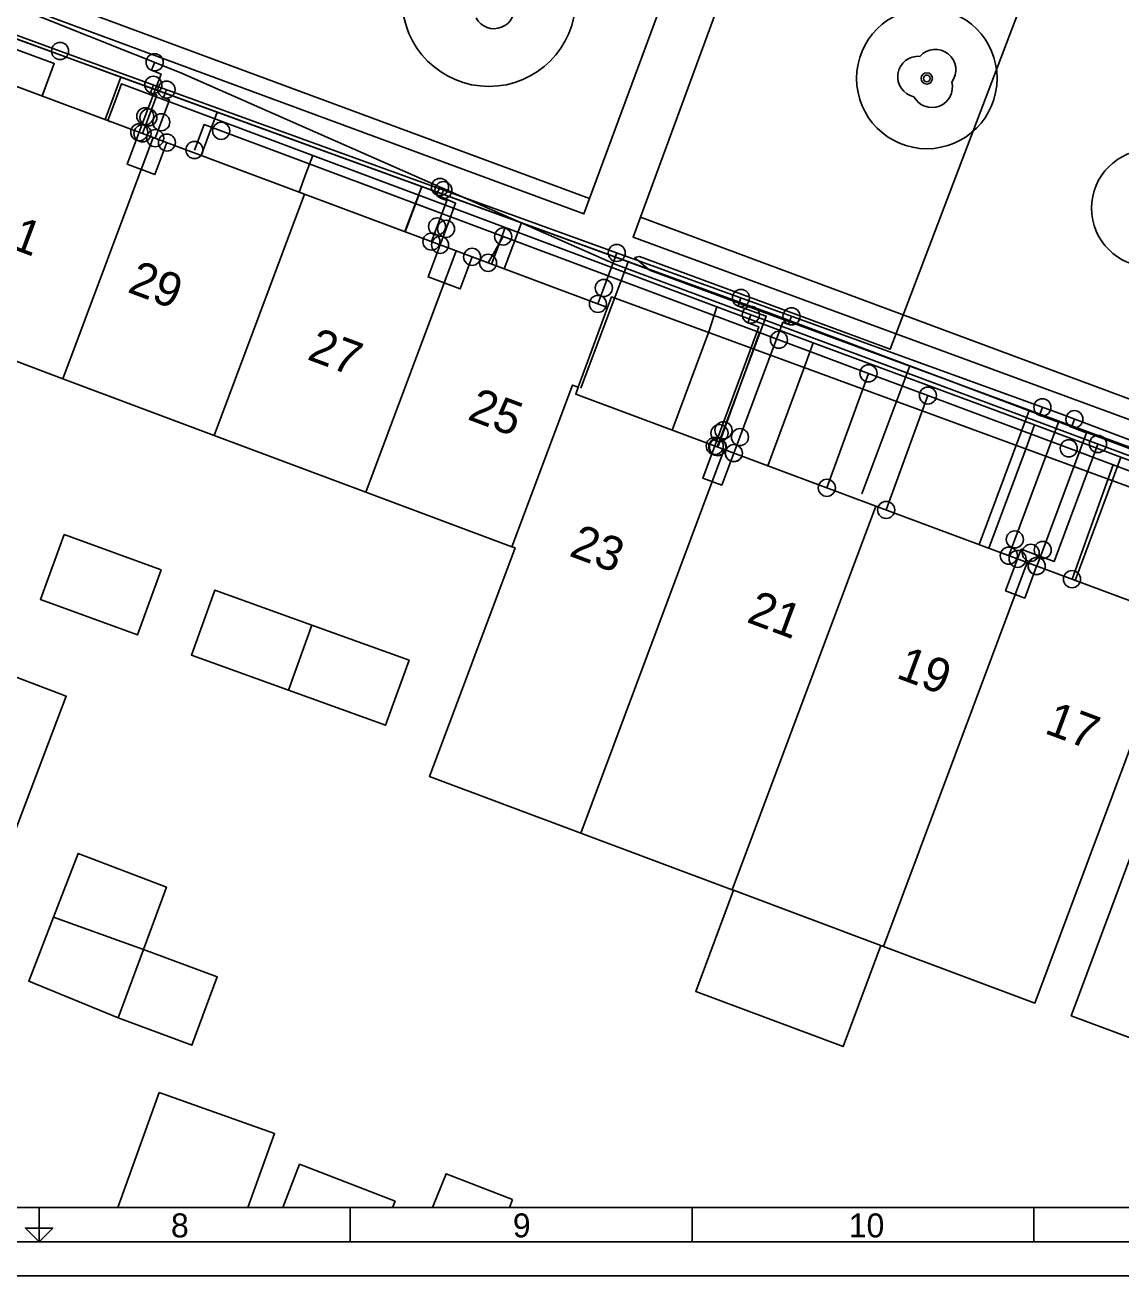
# Model space of a CAD drawing. Extents: x 192672 to 192910, y 446344 to 446512.
# Drawn here: x 192741.13 to 192773.19, y 446343.56 to 446380.14 of the extents above; entities that cross this region are included whole.
import ezdxf

# ---------------------------------------------------------------- set-up
doc = ezdxf.new("R2010")
doc.units = 0
for name, color, linetype in [('( Toegevoegd 29-11-2021 14_41_42) wegdeel vlak', 7, 'Continuous'), ('1010 viewport', 7, 'Continuous'), ('B-GV-GR-BOOM-S', 7, 'Continuous'), ('B-OI-KL-()_MANTELBUIS_WATER-G', 7, 'Continuous'), ('B-OI-KL-BUISLEIDING_OLIEGASCHEMICALIEN_GASLAGEDRUK-G', 7, 'Continuous'), ('B-OI-KL-DATA-G', 7, 'Continuous'), ('B-OI-KL-DATA_GTWP-S', 7, 'Continuous'), ('B-OI-KL-DATA_KABELBED-G', 7, 'Continuous'), ('B-OI-KL-DATA_MOF-S', 7, 'Continuous'), ('B-OI-KL-ET_LS-G', 7, 'Continuous'), ('B-OI-KL-ET_LS_DELIVERYPOINT-S', 7, 'Continuous'), ('B-OI-KL-ET_LS_MOF-S', 7, 'Continuous'), ('B-OI-KL-GAS_LD_AFTAKZADEL-S', 7, 'Continuous'), ('B-OI-KL-GAS_LD_DELIVERYPOINT-S', 7, 'Continuous'), ('B-OI-KL-GAS_LD_OVERGANGSSTUK-S', 7, 'Continuous'), ('B-OI-KL-WATER-G', 7, 'Continuous'), ('boom', 7, 'Continuous'), ('Default', 7, 'Continuous'), ('grens niveau plus 1', 7, 'Continuous'), ('huisnummerreeks BGT', 7, 'Continuous'), ('Luifel', 7, 'Continuous'), ('pand op maaiveld vlak', 7, 'Continuous'), ('straatnaam', 7, 'Continuous'), ('verkeerseiland - berm', 7, 'Continuous'), ('X-XX-AL-TEKENBLAD-S', 7, 'Continuous')]:
    doc.layers.add(name, color=color, linetype=linetype)

# ---------------------------------------------------------------- blocks, each defined once
blk = doc.blocks.new('B-OI-KL-GAS_LD_AFTAKZADEL-S')
at = {"layer": 'Default'}
blk.add_circle((0, 0), 0.25, dxfattribs=at)
blk = doc.blocks.new('B-OI-KL-GAS_LD_DELIVERYPOINT-S')
at = {"layer": 'Default'}
blk.add_circle((0, 0), 0.25, dxfattribs=at)
blk = doc.blocks.new('B-OI-KL-GAS_LD_OVERGANGSSTUK-S')
at = {"layer": 'Default'}
blk.add_circle((0, 0), 0.25, dxfattribs=at)
blk = doc.blocks.new('B-OI-KL-ET_LS_DELIVERYPOINT-S')
at = {"layer": 'Default'}
blk.add_circle((0, 0), 0.25, dxfattribs=at)
blk = doc.blocks.new('B-OI-KL-ET_LS_MOF-S')
at = {"layer": 'Default'}
blk.add_circle((0, 0), 0.25, dxfattribs=at)
blk = doc.blocks.new('B-OI-KL-DATA_GTWP-S')
at = {"layer": 'Default'}
blk.add_circle((0, 0), 0.25, dxfattribs=at)
blk = doc.blocks.new('B-OI-KL-DATA_MOF-S')
at = {"layer": 'Default'}
blk.add_circle((0, 0), 0.25, dxfattribs=at)

msp = doc.modelspace()

# ---------------------------------------------------------------- linework, layer by layer
at = {"layer": '( Toegevoegd 29-11-2021 14_41_42) wegdeel vlak'}
for points in [[(192744.875, 446390.822), (192741.123, 446380.652), (192757.478, 446374.617), (192757.644, 446375.067)], [(192759.13, 446374.517), (192758.916, 446373.935), (192776.422, 446367.504), (192776.611, 446368.02)], [(192758.17, 446371.875), (192758.285, 446372.185), (192775.949, 446365.705), (192777.106, 446365.279), (192794.631, 446358.595), (192794.529, 446358.306)]]:
    msp.add_lwpolyline(points, dxfattribs=at)
at = {"layer": '1010 viewport'}
msp.add_lwpolyline([(192675.743, 446509.756), (192860.643, 446509.756), (192860.643, 446345.556), (192675.743, 446345.556)], close=True, dxfattribs=at)
at = {"layer": 'B-GV-GR-BOOM-S'}
for centre, radius in [((192754.7, 446380.881), 2.539), ((192767.508, 446378.575), 2.054), ((192767.508, 446378.575), 0.164), ((192774.039, 446374.78), 1.713)]:
    msp.add_circle(centre, radius, dxfattribs=at)
at = {"layer": 'B-OI-KL-()_MANTELBUIS_WATER-G'}
msp.add_lwpolyline([(192741.735, 446378.347), (192741.63, 446378.066)], dxfattribs=at)
at = {"layer": 'B-OI-KL-BUISLEIDING_OLIEGASCHEMICALIEN_GASLAGEDRUK-G'}
for points in [[(192742.155, 446379.378), (192739.841, 446380.217), (192739.671, 446379.747)], [(192814.329, 446352.769), (192812.29, 446353.505), (192799.482, 446358.316), (192779.419, 446365.745), (192771.402, 446368.773), (192742.155, 446379.378)], [(192744.883, 446378.389), (192744.798, 446378.154), (192744.984, 446378.086), (192744.74, 446377.435)], [(192745.269, 446378.249), (192745.184, 446378.014), (192745.36, 446377.95), (192745.115, 446377.295)], [(192744.74, 446377.435), (192744.565, 446376.968)], [(192745.115, 446377.295), (192744.94, 446376.828)], [(192753.369, 446375.311), (192753.283, 446375.076), (192753.464, 446375.011), (192753.182, 446374.246)], [(192753.182, 446374.246), (192753.017, 446373.804)], [(192758.439, 446373.473), (192758.061, 446372.448)], [(192758.061, 446372.448), (192757.887, 446371.981)], [(192762.071, 446372.156), (192761.986, 446371.921), (192762.809, 446371.623), (192761.56, 446368.286)], [(192763.551, 446371.619), (192763.466, 446371.384), (192763.298, 446371.445), (192762.041, 446368.087)], [(192770.888, 446368.959), (192770.803, 446368.724), (192771.364, 446368.52), (192770.082, 446365.096)], [(192771.826, 446368.613), (192771.738, 446368.379), (192772.181, 446368.212), (192770.899, 446364.785)], [(192761.56, 446368.286), (192761.379, 446367.8)], [(192762.041, 446368.087), (192761.866, 446367.618)], [(192770.082, 446365.096), (192769.906, 446364.621)], [(192770.899, 446364.785), (192770.724, 446364.316)]]:
    msp.add_lwpolyline(points, dxfattribs=at)
at = {"layer": 'B-OI-KL-DATA-G'}
for points in [[(192777.905, 446365.29), (192778.164, 446365.987), (192777.507, 446366.23), (192773.332, 446367.794), (192762.994, 446371.683), (192740.707, 446379.788), (192739.862, 446380.106), (192736.793, 446371.939), (192730.818, 446355.23), (192731.661, 446354.909)], [(192731.661, 446354.909), (192730.818, 446355.23), (192736.793, 446371.939), (192739.862, 446380.106), (192740.707, 446379.788), (192762.994, 446371.683), (192773.332, 446367.794), (192777.507, 446366.23), (192792.515, 446360.708), (192794.868, 446359.138), (192813.343, 446352.261), (192813.029, 446351.418), (192812.66, 446350.461), (192825.476, 446345.665), (192825.435, 446345.556)], [(192825.435, 446345.556), (192825.476, 446345.665), (192812.66, 446350.461), (192813.029, 446351.418), (192813.343, 446352.261), (192794.868, 446359.138), (192792.515, 446360.708), (192777.507, 446366.23), (192773.332, 446367.794), (192762.994, 446371.683), (192740.707, 446379.788), (192739.862, 446380.106), (192736.793, 446371.939), (192730.818, 446355.23), (192731.661, 446354.909)], [(192731.661, 446354.909), (192730.818, 446355.23), (192736.793, 446371.939), (192739.862, 446380.106), (192740.707, 446379.788), (192762.994, 446371.683), (192773.332, 446367.794), (192777.507, 446366.23), (192792.515, 446360.708), (192794.868, 446359.138), (192813.343, 446352.261), (192813.029, 446351.418), (192812.66, 446350.461), (192825.476, 446345.665), (192825.435, 446345.556)], [(192825.435, 446345.556), (192825.476, 446345.665), (192812.66, 446350.461), (192813.029, 446351.418), (192813.343, 446352.261), (192794.868, 446359.138), (192792.515, 446360.708), (192777.507, 446366.23), (192773.332, 446367.794), (192762.994, 446371.683), (192740.707, 446379.788), (192739.862, 446380.106), (192736.793, 446371.939), (192730.818, 446355.23), (192731.661, 446354.909)], [(192825.435, 446345.556), (192825.476, 446345.665), (192812.66, 446350.461), (192813.029, 446351.418), (192813.343, 446352.261), (192794.868, 446359.138), (192792.515, 446360.708), (192777.507, 446366.23), (192773.332, 446367.794), (192762.994, 446371.683), (192740.707, 446379.788), (192739.862, 446380.106), (192736.793, 446371.939), (192730.818, 446355.23), (192731.661, 446354.909)], [(192825.435, 446345.556), (192825.476, 446345.665), (192812.66, 446350.461), (192813.029, 446351.418), (192813.343, 446352.261), (192794.868, 446359.138), (192792.515, 446360.708), (192777.507, 446366.23), (192773.332, 446367.794), (192762.994, 446371.683), (192740.707, 446379.788), (192739.862, 446380.106), (192736.793, 446371.939), (192730.818, 446355.23), (192731.661, 446354.909)], [(192825.435, 446345.556), (192825.476, 446345.665), (192812.66, 446350.461), (192813.029, 446351.418), (192813.343, 446352.261), (192794.868, 446359.138), (192792.515, 446360.708), (192777.507, 446366.23), (192773.332, 446367.794), (192762.994, 446371.683), (192740.707, 446379.788), (192739.862, 446380.106), (192736.793, 446371.939), (192730.818, 446355.23), (192731.661, 446354.909)], [(192731.661, 446354.909), (192730.818, 446355.23), (192736.793, 446371.939), (192739.862, 446380.106), (192740.707, 446379.788), (192762.994, 446371.683), (192773.332, 446367.794), (192777.507, 446366.23), (192792.515, 446360.708), (192794.868, 446359.138), (192813.343, 446352.261), (192813.029, 446351.418), (192812.66, 446350.461), (192825.476, 446345.665), (192825.435, 446345.556)], [(192731.661, 446354.909), (192730.818, 446355.23), (192736.793, 446371.939), (192739.862, 446380.106), (192740.707, 446379.788), (192762.994, 446371.683), (192773.332, 446367.794), (192777.507, 446366.23), (192792.515, 446360.708), (192794.868, 446359.138), (192813.343, 446352.261), (192813.029, 446351.418), (192812.66, 446350.461), (192825.476, 446345.665), (192825.435, 446345.556)], [(192825.435, 446345.556), (192825.476, 446345.665), (192812.66, 446350.461), (192813.029, 446351.418), (192813.343, 446352.261), (192794.868, 446359.138), (192792.515, 446360.708), (192777.507, 446366.23), (192773.332, 446367.794), (192762.994, 446371.683), (192740.707, 446379.788), (192739.862, 446380.106), (192736.793, 446371.939), (192730.818, 446355.23), (192731.661, 446354.909)], [(192825.435, 446345.556), (192825.476, 446345.665), (192812.66, 446350.461), (192813.029, 446351.418), (192813.343, 446352.261), (192794.868, 446359.138), (192792.515, 446360.708), (192777.507, 446366.23), (192773.332, 446367.794), (192762.994, 446371.683), (192740.707, 446379.788), (192739.862, 446380.106), (192736.793, 446371.939), (192730.818, 446355.23), (192731.661, 446354.909)], [(192777.905, 446365.29), (192778.164, 446365.987), (192777.507, 446366.23), (192773.332, 446367.794), (192762.994, 446371.683), (192740.707, 446379.788), (192739.862, 446380.106), (192736.793, 446371.939), (192732.637, 446360.318), (192733.582, 446359.958)], [(192777.905, 446365.29), (192778.164, 446365.987), (192777.507, 446366.23), (192773.332, 446367.794), (192762.994, 446371.683), (192743.934, 446378.615), (192743.471, 446377.378)], [(192749.547, 446376.324), (192743.956, 446378.419), (192743.764, 446377.908), (192743.555, 446377.346)], [(192777.905, 446365.29), (192778.164, 446365.987), (192777.507, 446366.23), (192773.332, 446367.794), (192762.994, 446371.683), (192746.754, 446377.589), (192746.281, 446376.326)], [(192743.6, 446377.3), (192743.555, 446377.346)], [(192749.547, 446376.324), (192749.357, 446375.815), (192749.146, 446375.253)], [(192752.653, 446375.164), (192749.547, 446376.324)], [(192777.905, 446365.29), (192778.164, 446365.987), (192777.507, 446366.23), (192773.332, 446367.794), (192762.994, 446371.683), (192752.734, 446375.414), (192752.241, 446374.095)], [(192752.653, 446375.164), (192752.251, 446374.091)], [(192755.178, 446374.215), (192752.653, 446375.164)], [(192777.905, 446365.29), (192778.164, 446365.987), (192777.507, 446366.23), (192773.332, 446367.794), (192762.994, 446371.683), (192755.648, 446374.354), (192755.144, 446373.008)], [(192755.178, 446374.215), (192754.988, 446373.707), (192754.778, 446373.145)], [(192761.365, 446371.892), (192755.178, 446374.215)], [(192777.905, 446365.29), (192778.164, 446365.987), (192777.507, 446366.23), (192773.332, 446367.794), (192762.994, 446371.683), (192758.775, 446373.217), (192757.385, 446369.519)], [(192761.365, 446371.892), (192761.139, 446371.191), (192760.058, 446368.293)], [(192764.185, 446370.844), (192761.365, 446371.892)], [(192764.185, 446370.844), (192763.932, 446370.14), (192762.855, 446367.25)], [(192770.655, 446368.444), (192764.185, 446370.844)], [(192777.905, 446365.29), (192778.164, 446365.987), (192777.507, 446366.23), (192773.332, 446367.794), (192767.014, 446370.171), (192765.606, 446366.426)], [(192777.905, 446365.29), (192778.164, 446365.987), (192777.507, 446366.23), (192773.332, 446367.794), (192770.497, 446368.861), (192769.037, 446364.945)], [(192770.655, 446368.444), (192770.417, 446367.768), (192769.325, 446364.838)], [(192773.185, 446367.497), (192770.655, 446368.444)], [(192773.185, 446367.497), (192772.921, 446366.782), (192771.846, 446363.898)], [(192780.217, 446364.871), (192773.185, 446367.497)]]:
    msp.add_lwpolyline(points, dxfattribs=at)
at = {"layer": 'B-OI-KL-DATA_KABELBED-G'}
for points in [[(192743.934, 446378.615), (192739.862, 446380.106), (192736.793, 446371.939), (192732.637, 446360.318)], [(192743.934, 446378.615), (192743.471, 446377.378)], [(192746.754, 446377.589), (192743.934, 446378.615)], [(192746.754, 446377.589), (192746.281, 446376.326)], [(192752.734, 446375.414), (192746.754, 446377.589)], [(192812.803, 446351.5), (192812.464, 446352.48), (192806.244, 446354.809), (192799.501, 446357.334), (192790.741, 446360.614), (192790.377, 446360.75), (192789.321, 446361.146), (192788.597, 446361.417), (192785.666, 446362.514), (192777.496, 446365.573), (192777.131, 446365.71), (192772.96, 446367.272), (192771.66, 446367.759), (192767.539, 446369.302), (192765.803, 446369.952), (192763.181, 446370.934), (192762.609, 446371.148), (192755.115, 446373.954), (192746.365, 446377.23), (192746.085, 446376.483)], [(192752.734, 446375.414), (192752.241, 446374.095)], [(192755.648, 446374.354), (192752.734, 446375.414)], [(192755.648, 446374.354), (192755.144, 446373.008)], [(192758.775, 446373.217), (192755.648, 446374.354)], [(192755.115, 446373.954), (192754.675, 446373.184)], [(192758.775, 446373.217), (192757.385, 446369.519)], [(192767.014, 446370.171), (192758.775, 446373.217)], [(192763.181, 446370.934), (192762.609, 446371.148), (192761.398, 446367.793)], [(192765.803, 446369.952), (192764.584, 446366.605)], [(192767.014, 446370.171), (192765.606, 446366.426)], [(192770.497, 446368.861), (192767.014, 446370.171)], [(192767.539, 446369.302), (192766.32, 446365.958)], [(192770.497, 446368.861), (192769.037, 446364.945)], [(192775.977, 446366.803), (192770.497, 446368.861)], [(192771.66, 446367.759), (192772.96, 446367.272), (192771.755, 446363.932)]]:
    msp.add_lwpolyline(points, dxfattribs=at)
at = {"layer": 'B-OI-KL-ET_LS-G'}
for points in [[(192773.186, 446389.136), (192773.068, 446389.1), (192772.926, 446389.144), (192770.278, 446380.756), (192766.438, 446370.656), (192759.102, 446373.366), (192758.958, 446373.34)], [(192812.885, 446353.609), (192808.475, 446355.248), (192804.025, 446356.797), (192795.126, 446359.954), (192777.441, 446366.051), (192758.408, 446373.136), (192745.69, 446378.74), (192740.34, 446380.878), (192731.982, 446384.732), (192732.765, 446387.575)], [(192744.922, 446379.047), (192744.83, 446378.815), (192745.108, 446378.703), (192744.646, 446377.471)], [(192744.646, 446377.471), (192744.472, 446377.003)], [(192744.472, 446377.003), (192744.121, 446376.067), (192744.93, 446375.764), (192745.28, 446376.701)], [(192753.268, 446375.401), (192753.168, 446375.172), (192753.726, 446374.926), (192753.446, 446374.178)], [(192753.446, 446374.178), (192753.271, 446373.709)], [(192753.271, 446373.709), (192752.92, 446372.773), (192753.857, 446372.422), (192754.207, 446373.359)], [(192758.958, 446373.34), (192759.392, 446372.967), (192781.93, 446364.664)], [(192762.36, 446371.665), (192762.273, 446371.43), (192762.59, 446371.312), (192761.444, 446368.203)], [(192761.444, 446368.203), (192761.304, 446367.828)], [(192761.304, 446367.828), (192760.955, 446366.891), (192761.514, 446366.682), (192761.864, 446367.619)], [(192772.514, 446367.885), (192771.23, 446364.453), (192770.548, 446364.702)], [(192770.548, 446364.702), (192770.267, 446364.807), (192770.162, 446364.526)], [(192770.162, 446364.526), (192769.813, 446363.589), (192770.372, 446363.38), (192770.721, 446364.317)]]:
    msp.add_lwpolyline(points, dxfattribs=at)
at = {"layer": 'B-OI-KL-WATER-G'}
msp.add_lwpolyline([(192730.071, 446383.458), (192740.795, 446379.447), (192741.984, 446379.012), (192741.63, 446378.066)], dxfattribs=at)
at = {"layer": 'boom'}
msp.add_circle((192767.508, 446378.575), 0.1, dxfattribs=at)
for centre, radius, start, end in [((192754.85, 446380.631), 0.6, 208.5058, 13.8356), ((192767.758, 446378.825), 0.6, 323.5446, 138.4658), ((192767.258, 446378.625), 0.6, 85.137, 257.7544), ((192767.508, 446378.575), 0.1, 0, 180), ((192767.658, 446378.325), 0.6, 208.5058, 13.8356), ((192767.508, 446378.575), 0.1, 180, 0)]:
    msp.add_arc(centre, radius, start, end, dxfattribs=at)
at = {"layer": 'grens niveau plus 1'}
msp.add_line((192745.049, 446348.922), (192743.84, 446345.556), dxfattribs=at)
msp.add_lwpolyline([(192747.65, 446345.556), (192748.43, 446347.726), (192745.049, 446348.922)], dxfattribs=at)
at = {"layer": 'Luifel'}
for points in [[(192766.166, 446353.222), (192765.058, 446350.263), (192760.747, 446351.877), (192761.855, 446354.836)], [(192743.852, 446351.105), (192746.012, 446350.305), (192746.753, 446352.307), (192744.593, 446353.107)]]:
    msp.add_lwpolyline(points, dxfattribs=at)
at = {"layer": 'pand op maaiveld vlak'}
for p, q in [((192740.444, 446378.51), (192744.876, 446376.852)), ((192744.876, 446376.852), (192742.235, 446369.796)), ((192749.307, 446375.193), (192744.876, 446376.852)), ((192749.307, 446375.193), (192746.666, 446368.138)), ((192749.307, 446375.193), (192753.739, 446373.534)), ((192753.739, 446373.534), (192751.098, 446366.48)), ((192753.739, 446373.534), (192758.17, 446371.875)), ((192758.17, 446371.875), (192757.312, 446369.547)), ((192737.803, 446371.456), (192742.235, 446369.796)), ((192742.235, 446369.796), (192746.666, 446368.138)), ((192746.666, 446368.138), (192751.098, 446366.48)), ((192757.388, 446356.507), (192761.585, 446367.723)), ((192761.585, 446367.723), (192766.014, 446366.072)), ((192755.366, 446364.882), (192751.098, 446366.48)), ((192766.014, 446366.072), (192761.814, 446354.851)), ((192770.443, 446364.421), (192766.014, 446366.072)), ((192766.241, 446353.194), (192770.443, 446364.421)), ((192749.523, 446362.586), (192748.837, 446360.686)), ((192757.388, 446356.507), (192761.814, 446354.851)), ((192761.855, 446354.836), (192761.814, 446354.851)), ((192766.166, 446353.222), (192761.855, 446354.836)), ((192744.593, 446353.107), (192741.961, 446354.044)), ((192743.852, 446351.105), (192744.593, 446353.107)), ((192766.241, 446353.194), (192766.166, 446353.222)), ((192749.154, 446346.827), (192748.671, 446345.556)), ((192755.301, 446345.556), (192755.392, 446345.788))]:
    msp.add_line(p, q, dxfattribs=at)
for points in [[(192755.366, 446364.882), (192757.145, 446369.61), (192757.312, 446369.547)], [(192761.585, 446367.723), (192757.237, 446369.345), (192757.312, 446369.547)], [(192742.273, 446365.238), (192741.579, 446363.341), (192744.415, 446362.304), (192745.109, 446364.201), (192742.273, 446365.238)], [(192755.366, 446364.882), (192755.462, 446364.846), (192752.961, 446358.164), (192757.388, 446356.507)], [(192766.241, 446353.194), (192770.667, 446351.537), (192774.871, 446362.77), (192770.443, 446364.421)], [(192740.119, 446354.688), (192742.334, 446360.51), (192734.872, 446363.349)], [(192749.523, 446362.586), (192746.682, 446363.612), (192745.996, 446361.712), (192748.837, 446360.686)], [(192749.523, 446362.586), (192752.364, 446361.56), (192751.678, 446359.66), (192748.837, 446360.686)], [(192780.333, 446360.728), (192775.916, 446362.375), (192771.735, 446351.16), (192776.152, 446349.513)], [(192744.593, 446353.107), (192745.266, 446354.926), (192742.68, 446355.914), (192741.961, 446354.044)], [(192743.852, 446351.105), (192741.241, 446352.173), (192741.961, 446354.044)], [(192751.883, 446345.556), (192751.953, 446345.74), (192749.154, 446346.827)], [(192755.392, 446345.788), (192753.448, 446346.547), (192753.05, 446345.556)]]:
    msp.add_lwpolyline(points, dxfattribs=at)
at = {"layer": 'verkeerseiland - berm'}
for p, q in [((192761.203, 446384.713), (192757.644, 446375.067)), ((192762.674, 446384.166), (192759.13, 446374.517)), ((192759.13, 446374.517), (192776.611, 446368.02))]:
    msp.add_line(p, q, dxfattribs=at)
msp.add_lwpolyline([(192745.382, 446390.635), (192741.79, 446380.939), (192757.644, 446375.067)], dxfattribs=at)
at = {"layer": 'X-XX-AL-TEKENBLAD-S'}
for p, q in [((192741.543, 446345.556), (192741.543, 446344.556)), ((192750.643, 446344.556), (192750.643, 446345.556)), ((192760.643, 446344.556), (192760.643, 446345.556)), ((192770.643, 446344.556), (192770.643, 446345.556)), ((192741.543, 446344.956), (192741.543, 446344.556)), ((192741.543, 446344.556), (192741.543, 446344.956)), ((192674.743, 446344.556), (192908.543, 446344.556)), ((192671.743, 446343.556), (192909.543, 446343.556))]:
    msp.add_line(p, q, dxfattribs=at)
msp.add_lwpolyline([(192675.743, 446345.556), (192907.543, 446345.556), (192907.543, 446509.756), (192675.743, 446509.756)], close=True, dxfattribs=at)
for points in [[(192741.543, 446344.556), (192741.143, 446344.956), (192741.543, 446344.956)], [(192741.543, 446344.956), (192741.943, 446344.956), (192741.543, 446344.556)]]:
    msp.add_lwpolyline(points, dxfattribs=at)

# ---------------------------------------------------------------- block references
at = {"layer": 'B-OI-KL-DATA_GTWP-S'}
for p in [(192746.085, 446376.483), (192755.115, 446373.954), (192754.675, 446373.184), (192763.181, 446370.934), (192765.803, 446369.952), (192767.539, 446369.302), (192761.398, 446367.793), (192771.66, 446367.759), (192764.584, 446366.605), (192766.32, 446365.958), (192771.755, 446363.932)]:
    msp.add_blockref('B-OI-KL-DATA_GTWP-S', p, dxfattribs=at)
at = {"layer": 'B-OI-KL-DATA_MOF-S'}
for p in [(192746.866, 446377.043), (192755.115, 446373.954), (192763.181, 446370.934), (192765.803, 446369.952), (192767.539, 446369.302), (192771.66, 446367.759)]:
    msp.add_blockref('B-OI-KL-DATA_MOF-S', p, dxfattribs=at)
at = {"layer": 'B-OI-KL-ET_LS_DELIVERYPOINT-S'}
for p in [(192744.472, 446377.003), (192745.28, 446376.701), (192753.271, 446373.709), (192754.207, 446373.359), (192761.304, 446367.828), (192761.864, 446367.619), (192770.162, 446364.526), (192770.721, 446364.317)]:
    msp.add_blockref('B-OI-KL-ET_LS_DELIVERYPOINT-S', p, dxfattribs=at)
at = {"layer": 'B-OI-KL-ET_LS_MOF-S'}
for p in [(192744.922, 446379.047), (192744.646, 446377.471), (192753.268, 446375.401), (192753.446, 446374.178), (192762.36, 446371.665), (192761.444, 446368.203), (192772.514, 446367.885), (192770.548, 446364.702)]:
    msp.add_blockref('B-OI-KL-ET_LS_MOF-S', p, dxfattribs=at)
at = {"layer": 'B-OI-KL-GAS_LD_AFTAKZADEL-S'}
for p in [(192744.883, 446378.389), (192745.269, 446378.249), (192753.369, 446375.311), (192758.439, 446373.473), (192762.071, 446372.156), (192763.551, 446371.619), (192770.888, 446368.959), (192771.826, 446368.613)]:
    msp.add_blockref('B-OI-KL-GAS_LD_AFTAKZADEL-S', p, dxfattribs=at)
at = {"layer": 'B-OI-KL-GAS_LD_DELIVERYPOINT-S'}
for p in [(192744.565, 446376.968), (192744.94, 446376.828), (192753.017, 446373.804), (192757.887, 446371.981), (192761.379, 446367.8), (192761.866, 446367.618), (192769.906, 446364.621), (192770.724, 446364.316)]:
    msp.add_blockref('B-OI-KL-GAS_LD_DELIVERYPOINT-S', p, dxfattribs=at)
at = {"layer": 'B-OI-KL-GAS_LD_OVERGANGSSTUK-S'}
for p in [(192742.155, 446379.378), (192744.74, 446377.435), (192745.115, 446377.295), (192753.182, 446374.246), (192758.061, 446372.448), (192761.56, 446368.286), (192762.041, 446368.087), (192770.082, 446365.096), (192770.899, 446364.785)]:
    msp.add_blockref('B-OI-KL-GAS_LD_OVERGANGSSTUK-S', p, dxfattribs=at)

# ---------------------------------------------------------------- texts
at = {"layer": 'huisnummerreeks BGT'}
for s, rotation, p in [('31', 339.5, (192739.979, 446373.88)), ('29', 339.5, (192744.094, 446372.34)), ('27', 339.5, (192749.348, 446370.373)), ('25', 339.5, (192754.039, 446368.617)), ('23', 339.6, (192757.013, 446364.626)), ('21', 339.6, (192762.203, 446362.69)), ('19', 339.6, (192766.578, 446361.059)), ('17', 339.6, (192770.915, 446359.442))]:
    msp.add_text(s, height=1, rotation=rotation, dxfattribs=at).set_placement(p)
at = {"layer": 'straatnaam'}
msp.add_text('Fokke Noordhoffstraat', height=2, rotation=340.2, dxfattribs=at).set_placement((192764.533, 446387.236))
at = {"layer": 'X-XX-AL-TEKENBLAD-S'}
for s, p in [('8', (192745.399, 446344.685)), ('9', (192755.399, 446344.685)), ('10', (192765.224, 446344.685))]:
    msp.add_text(s, height=0.7, dxfattribs=at).set_placement(p)

doc.saveas('drawing.dxf')
